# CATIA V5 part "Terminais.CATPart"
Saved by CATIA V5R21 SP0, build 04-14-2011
Part number: Terminais
Definition: Terminais
Nomenclature: Terminais
Source: Unknown
Bounding box of the stored display mesh (mm): x -0.2 to 0.2, y 0 to 4.25, z -1 to 1
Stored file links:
  C:\Users\beatr\OneDrive\Documents\UNB\2026_1\Pi1\Componentes eletronicos\Terminais.CATPart
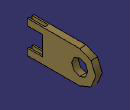
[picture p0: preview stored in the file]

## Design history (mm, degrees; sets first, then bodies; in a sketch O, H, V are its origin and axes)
Body1 "Sólido1" (main body)
  Solid1: solid without history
